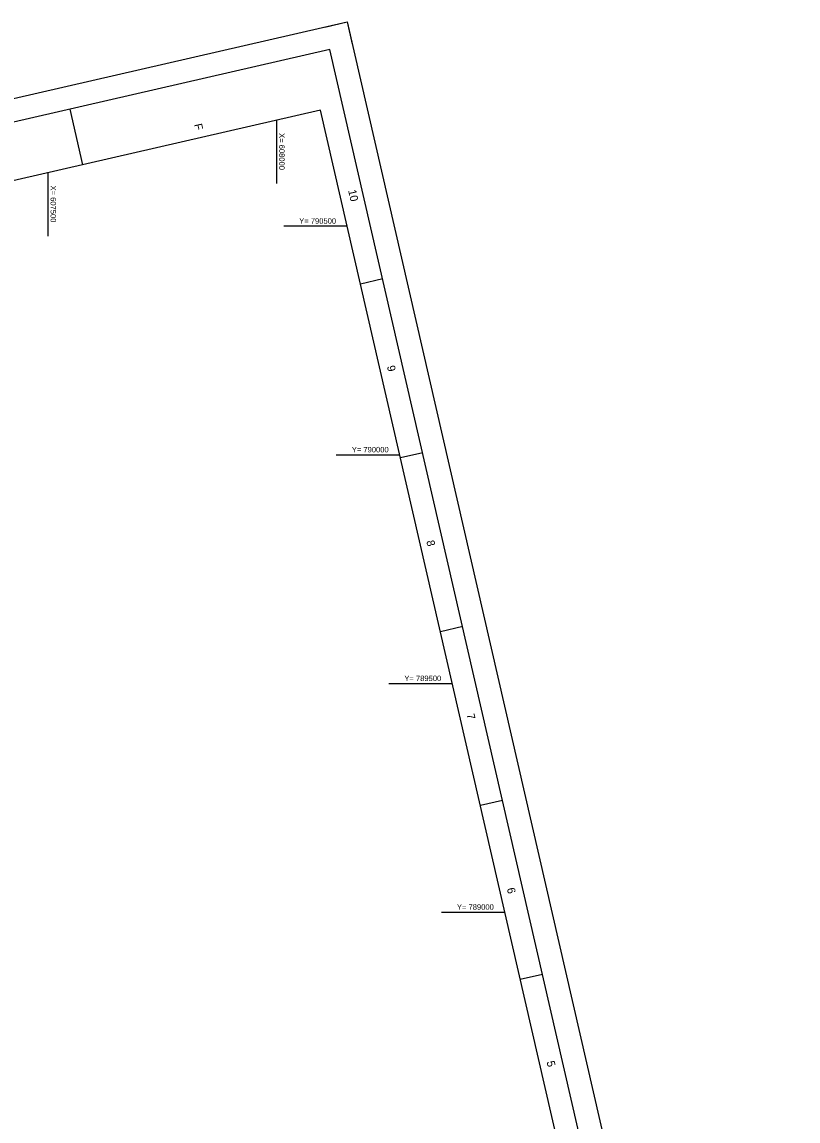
# Model space of a CAD drawing. Extents: x 604840 to 609139, y 785896 to 790946.
# Drawn here: x 607443 to 609139, y 788543 to 790946 of the extents above; entities that cross this region are included whole.
import ezdxf

# ---------------------------------------------------------------- set-up
doc = ezdxf.new("R2010")
doc.units = 0
for name, color, linetype in [('Default', 7, 'Continuous'), ('G-ANNO-NPLT', 7, 'Continuous'), ('G-ANNO-TTLB', 7, 'Continuous'), ('V-TOPO-COOR-STAT', 7, 'Continuous')]:
    doc.layers.add(name, color=color, linetype=linetype)

msp = doc.modelspace()

# ---------------------------------------------------------------- linework, layer by layer
at = {"layer": 'G-ANNO-NPLT'}
msp.add_lwpolyline([(608153.4, 790946.1), (609138.7, 786657.8), (605825.1, 785896.5), (604839.8, 790184.7)], close=True, dxfattribs=at)
msp.add_lwpolyline([(608104.7, 790934.9), (608153.4, 790946.1), (608164.6, 790897.3)], dxfattribs=at)
at = {"layer": 'G-ANNO-TTLB'}
for p, q in [((607547.2, 790755.5), (607575.2, 790633.6)), ((608231.2, 790384.2), (608182.5, 790373)), ((608318.5, 790004.1), (608269.8, 789992.9)), ((608318.5, 790004.1), (608269.8, 789992.9)), ((608405.9, 789624), (608357.1, 789612.8)), ((608493.2, 789243.9), (608444.5, 789232.7)), ((608580.5, 788863.8), (608531.8, 788852.6))]:
    msp.add_line(p, q, dxfattribs=at)
for points in [[(604899.7, 790147.2), (605862.6, 785956.4), (609078.8, 786695.3), (608115.9, 790886.1)], [(609018.8, 786732.9), (608095.1, 790753.1), (604976.4, 790036.5), (605900.1, 786016.3)]]:
    msp.add_lwpolyline(points, close=True, dxfattribs=at)
at = {"layer": 'V-TOPO-COOR-STAT'}
for p, q in [((608000, 790592.7), (608000, 790731.2)), ((607500, 790477.8), (607500, 790616.4)), ((608014.8, 790500), (608153.3, 790500)), ((608129.6, 790000), (608268.2, 790000)), ((608244.5, 789500), (608383, 789500)), ((608359.4, 789000), (608497.9, 789000))]:
    msp.add_line(p, q, dxfattribs=at)

# ---------------------------------------------------------------- texts
at = {"layer": 'Default'}
msp.add_text('X= 608000', height=12, rotation=270, dxfattribs=at).set_placement((608004.7, 790703.1))
at = {"layer": 'G-ANNO-TTLB'}
for s, p in [('F', (607818.7, 790721.9)), ('10', (608155.4, 790577.6)), ('9', (608240.2, 790193)), ('8', (608326.3, 789810.8)), ('7', (608414, 789432.1)), ('6', (608502.3, 789051.3)), ('5', (608589.2, 788672.7))]:
    msp.add_text(s, height=17.5, rotation=282.9401, dxfattribs=at).set_placement(p)
at = {"layer": 'V-TOPO-COOR-STAT'}
msp.add_text('X= 607500', height=12, rotation=270, dxfattribs=at).set_placement((607505.2, 790588.4))
for s, p in [('Y= 790500', (608048.6, 790505)), ('Y= 790000', (608163.5, 790005)), ('Y= 789500', (608278.4, 789505)), ('Y= 789000', (608393.3, 789005))]:
    msp.add_text(s, height=12, dxfattribs=at).set_placement(p)

doc.saveas('drawing.dxf')
